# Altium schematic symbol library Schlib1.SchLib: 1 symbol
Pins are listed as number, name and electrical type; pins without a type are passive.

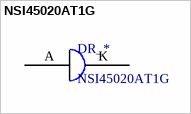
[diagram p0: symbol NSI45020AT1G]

## NSI45020AT1G
designator DR_*
footprint NSI45020AT1G
pins: A 0, K 1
